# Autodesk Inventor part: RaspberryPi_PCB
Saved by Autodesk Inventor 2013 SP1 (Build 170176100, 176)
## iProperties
Created: 2013-01
Part Number: RaspberryPi_PCB
Material: Generic
Document SubType Name: Modeling
Designer: Kevin
Density: 1 g/cm^3
Author: Kevin
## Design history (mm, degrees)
node "RaspberryPi_PCB1"
node "RaspberryPi_PCB"
node "Base1"
